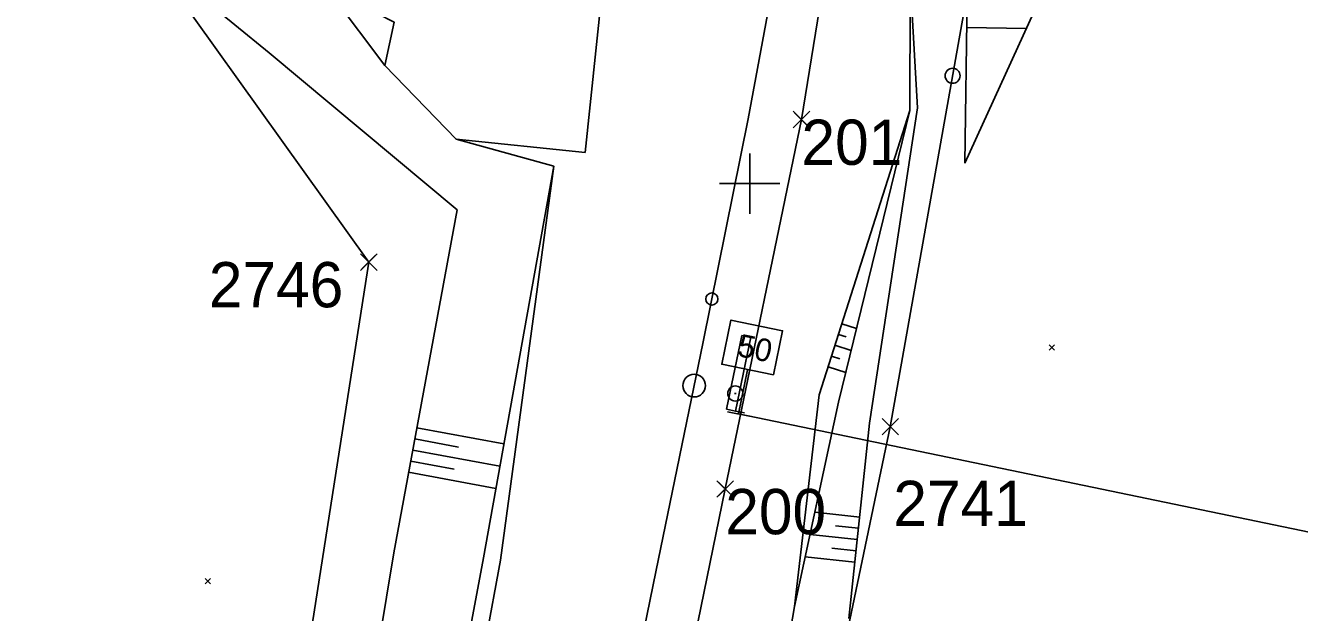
# Model space of a CAD drawing. Extents: x -866402 to -860377, y -1041908 to -1038598.
# Drawn here: x -864148.1 to -864063.5, y -1040828.4 to -1040789.5 of the extents above; entities that cross this region are included whole.
import ezdxf

# ---------------------------------------------------------------- set-up
doc = ezdxf.new("R2010")
doc.units = 0
for name, color, linetype in [('PS 02 trasa', 7, 'Continuous'), ('SZDC', 7, 'Continuous'), ('Vrstva 1', 7, 'Continuous'), ('Vrstva 17', 7, 'Continuous'), ('Vrstva 36', 7, 'Continuous'), ('Vrstva 48', 7, 'Continuous'), ('Vrstva 49', 7, 'Continuous'), ('Vrstva 5', 7, 'Continuous'), ('Vrstva 60', 7, 'Continuous'), ('Vrstva 7', 7, 'Continuous'), ('Vrstva 9', 7, 'Continuous')]:
    doc.layers.add(name, color=color, linetype=linetype)

msp = doc.modelspace()

# ---------------------------------------------------------------- linework, layer by layer
at = {"layer": 'PS 02 trasa'}
msp.add_lwpolyline([(-864121.797, -1040918.2), (-864117.134, -1040893.882), (-864111.832, -1040869.24), (-864106.624, -1040844.668), (-864101.618, -1040820.256), (-864096.565, -1040795.762), (-864092.572, -1040771.202), (-864089.365, -1040745.718), (-864088.857, -1040741.962), (-864088.53, -1040729.9), (-864086.691, -1040725.001), (-864086.691, -1040721.224), (-864088.129, -1040715.124), (-864088.084, -1040713.449), (-864089.947, -1040685.182), (-864092.443, -1040667.814), (-864096.732, -1040643.485)], dxfattribs=at)
at = {"layer": 'SZDC'}
for points in [[(-864163.471, -1040355.801), (-864153.108, -1040402.253), (-864151.773, -1040408.236), (-864141.636, -1040383.5), (-864136.164, -1040395.654), (-864121.344, -1040428.573), (-864124.994, -1040437.136), (-864137.005, -1040440.857), (-864126.473, -1040480.602), (-864126.25, -1040482.627), (-864122.508, -1040516.53), (-864121.023, -1040529.985), (-864108.772, -1040562.648), (-864093.709, -1040623.913), (-864080.868, -1040663.902), (-864070.496, -1040699.085), (-864073.496, -1040728.47), (-864078.356, -1040748.127), (-864079.126, -1040751.243), (-864090.668, -1040816.124), (-864108.728, -1040902.455), (-864114.595, -1040901.241), (-864124.203, -1040948.655)], [(-864151.935, -1040958.113), (-864146.262, -1040929.776), (-864137.277, -1040882.021), (-864125.279, -1040805.208), (-864144.051, -1040778.984), (-864138.75, -1040728.98)]]:
    msp.add_lwpolyline(points, dxfattribs=at)
at = {"layer": 'Vrstva 1'}
for points in [[(-864106.236, -1040825.758), (-864103.089, -1040810.503), (-864100.1, -1040795.717), (-864097.364, -1040780.894), (-864095.106, -1040765.445), (-864093.483, -1040749.153), (-864092.628, -1040733.442), (-864092.48, -1040717.354), (-864093.092, -1040701.61), (-864094.533, -1040685.034), (-864096.789, -1040668.551), (-864099.734, -1040652.551), (-864103.197, -1040636.581), (-864106.87, -1040620.665), (-864110.466, -1040605.214), (-864116.495, -1040579.331)], [(-864190.897, -1041239.893), (-864187.654, -1041224.26), (-864179.077, -1041182.252), (-864176.192, -1041168.165), (-864167.631, -1041126.213), (-864158.946, -1041083.668), (-864157.987, -1041079.013), (-864156.213, -1041070.305), (-864147.519, -1041027.821), (-864138.927, -1040985.783), (-864136.16, -1040972.299), (-864133.068, -1040957.148), (-864132.451, -1040954.143), (-864131.095, -1040947.46), (-864122.536, -1040905.522), (-864114.141, -1040864.418), (-864106.236, -1040825.758)]]:
    msp.add_lwpolyline(points, dxfattribs=at)
msp.add_circle((-864102.514, -1040807.658), 0.4, dxfattribs=at)
at = {"layer": 'Vrstva 17'}
msp.add_line((-864108.311, -1040773.317), (-864110.918, -1040797.952), dxfattribs=at)
msp.add_lwpolyline([(-864110.918, -1040797.952), (-864119.472, -1040797.069), (-864124.216, -1040792.181), (-864123.595, -1040789.29), (-864128.105, -1040786.988)], dxfattribs=at)
at = {"layer": 'Vrstva 36'}
msp.add_circle((-864086.533, -1040792.855), 0.5, dxfattribs=at)
at = {"layer": 'Vrstva 48'}
for p, q in [((-864085.604, -1040789.661), (-864081.63, -1040789.711)), ((-864093.887, -1040809.295), (-864092.907, -1040809.607)), ((-864094.115, -1040810.009), (-864093.6, -1040810.173)), ((-864094.343, -1040810.724), (-864093.264, -1040811.068)), ((-864094.57, -1040811.438), (-864094.006, -1040811.618)), ((-864094.798, -1040812.153), (-864093.62, -1040812.529)), ((-864122.084, -1040816.199), (-864116.305, -1040817.272)), ((-864122.221, -1040816.937), (-864119.329, -1040817.473)), ((-864122.358, -1040817.674), (-864116.571, -1040818.748)), ((-864122.494, -1040818.412), (-864119.599, -1040818.949)), ((-864122.631, -1040819.149), (-864116.837, -1040820.224)), ((-864092.7, -1040822.117), (-864095.676, -1040821.802)), ((-864092.779, -1040822.862), (-864094.307, -1040822.701)), ((-864092.858, -1040823.608), (-864095.994, -1040823.277)), ((-864092.937, -1040824.354), (-864094.545, -1040824.184)), ((-864093.016, -1040825.1), (-864096.312, -1040824.751))]:
    msp.add_line(p, q, dxfattribs=at)
at = {"layer": 'Vrstva 49'}
for p, q in [((-864131.892, -1040791.324), (-864142.841, -1040782.399)), ((-864085.718, -1040798.649), (-864085.529, -1040783.803)), ((-864085.718, -1040798.649), (-864079.565, -1040785.195)), ((-864124.216, -1040792.181), (-864128.105, -1040786.988)), ((-864089.34, -1040786.677), (-864089.382, -1040795.164)), ((-864088.859, -1040794.982), (-864089.34, -1040786.677)), ((-864119.403, -1040801.754), (-864131.892, -1040791.324)), ((-864119.472, -1040797.069), (-864124.216, -1040792.181)), ((-864088.859, -1040794.982), (-864092.042, -1040815.892)), ((-864095.389, -1040814.006), (-864089.382, -1040795.164)), ((-864094.1, -1040814.495), (-864089.382, -1040795.164)), ((-864112.989, -1040798.838), (-864119.472, -1040797.069)), ((-864117.662, -1040824.812), (-864112.989, -1040798.838)), ((-864116.527, -1040824.975), (-864112.989, -1040798.838)), ((-864123.621, -1040824.482), (-864119.403, -1040801.754)), ((-864080.129, -1040810.69), (-864079.775, -1040811.044)), ((-864080.129, -1040811.044), (-864079.775, -1040810.69)), ((-864097.023, -1040828.045), (-864095.389, -1040814.006)), ((-864097.023, -1040828.045), (-864094.1, -1040814.495)), ((-864093.412, -1040828.85), (-864092.042, -1040815.892)), ((-864123.621, -1040824.482), (-864129.658, -1040861.451)), ((-864124.858, -1040863.393), (-864117.662, -1040824.812)), ((-864123.555, -1040862.726), (-864116.527, -1040824.975)), ((-864136.137, -1040826.2), (-864135.783, -1040826.554)), ((-864136.137, -1040826.554), (-864135.783, -1040826.2)), ((-864103.151, -1040862.883), (-864097.023, -1040828.045))]:
    msp.add_line(p, q, dxfattribs=at)
at = {"layer": 'Vrstva 5'}
for p, q in [((-864100, -1040798), (-864100, -1040802)), ((-864102, -1040800), (-864098, -1040800)), ((-864100.741, -1040815.282), (-864100.135, -1040812.344)), ((-864101.476, -1040815.13), (-864100.006, -1040815.434)), ((-864100.741, -1040815.282), (-864045.186, -1040826.793))]:
    msp.add_line(p, q, dxfattribs=at)
msp.add_lwpolyline([(-864098.421, -1040812.697), (-864101.849, -1040811.99), (-864101.243, -1040809.052), (-864097.815, -1040809.759)], close=True, dxfattribs=at)
at = {"layer": 'Vrstva 60'}
for p, q in [((-864096.115, -1040796.212), (-864097.115, -1040795.212)), ((-864096.115, -1040795.312), (-864097.115, -1040796.312)), ((-864097.015, -1040796.212), (-864096.015, -1040795.212)), ((-864097.015, -1040795.312), (-864096.015, -1040796.312)), ((-864096.565, -1040795.762), (-864096.565, -1040795.762)), ((-864124.829, -1040805.658), (-864125.829, -1040804.658)), ((-864124.829, -1040804.758), (-864125.829, -1040805.758)), ((-864125.729, -1040805.658), (-864124.729, -1040804.658)), ((-864125.729, -1040804.758), (-864124.729, -1040805.758)), ((-864125.279, -1040805.208), (-864125.279, -1040805.208)), ((-864090.218, -1040816.574), (-864091.218, -1040815.574)), ((-864090.218, -1040815.674), (-864091.218, -1040816.674)), ((-864091.118, -1040816.574), (-864090.118, -1040815.574)), ((-864091.118, -1040815.674), (-864090.118, -1040816.674)), ((-864090.668, -1040816.124), (-864090.668, -1040816.124)), ((-864101.168, -1040820.706), (-864102.168, -1040819.706)), ((-864101.168, -1040819.806), (-864102.168, -1040820.806)), ((-864102.068, -1040820.706), (-864101.068, -1040819.706)), ((-864102.068, -1040819.806), (-864101.068, -1040820.806)), ((-864101.618, -1040820.256), (-864101.618, -1040820.256))]:
    msp.add_line(p, q, dxfattribs=at)
at = {"layer": 'Vrstva 7'}
msp.add_line((-864101.004, -1040813.922), (-864100.904, -1040813.922), dxfattribs=at)
for centre, radius in [((-864103.687, -1040813.402), 0.75), ((-864100.954, -1040813.922), 0.5)]:
    msp.add_circle(centre, radius, dxfattribs=at)
at = {"layer": 'Vrstva 9'}
for p, q in [((-864100.517, -1040810.073), (-864101.527, -1040814.969)), ((-864100.939, -1040815.091), (-864099.929, -1040810.194)), ((-864099.929, -1040810.194), (-864100.517, -1040810.073)), ((-864101.527, -1040814.969), (-864100.939, -1040815.091)), ((-864100.939, -1040815.091), (-864100.352, -1040815.212))]:
    msp.add_line(p, q, dxfattribs=at)

# ---------------------------------------------------------------- texts
at = {"layer": 'Vrstva 5'}
msp.add_text('50', height=1.5, rotation=348.3438, dxfattribs=at).set_placement((-864100.878, -1040811.425))
at = {"layer": 'Vrstva 60'}
for s, p in [('201', (-864096.565, -1040798.762)), ('2746', (-864135.889, -1040808.208)), ('200', (-864101.618, -1040823.256)), ('2741', (-864090.467, -1040822.714))]:
    msp.add_text(s, height=3, dxfattribs=at).set_placement(p)

doc.saveas('drawing.dxf')
